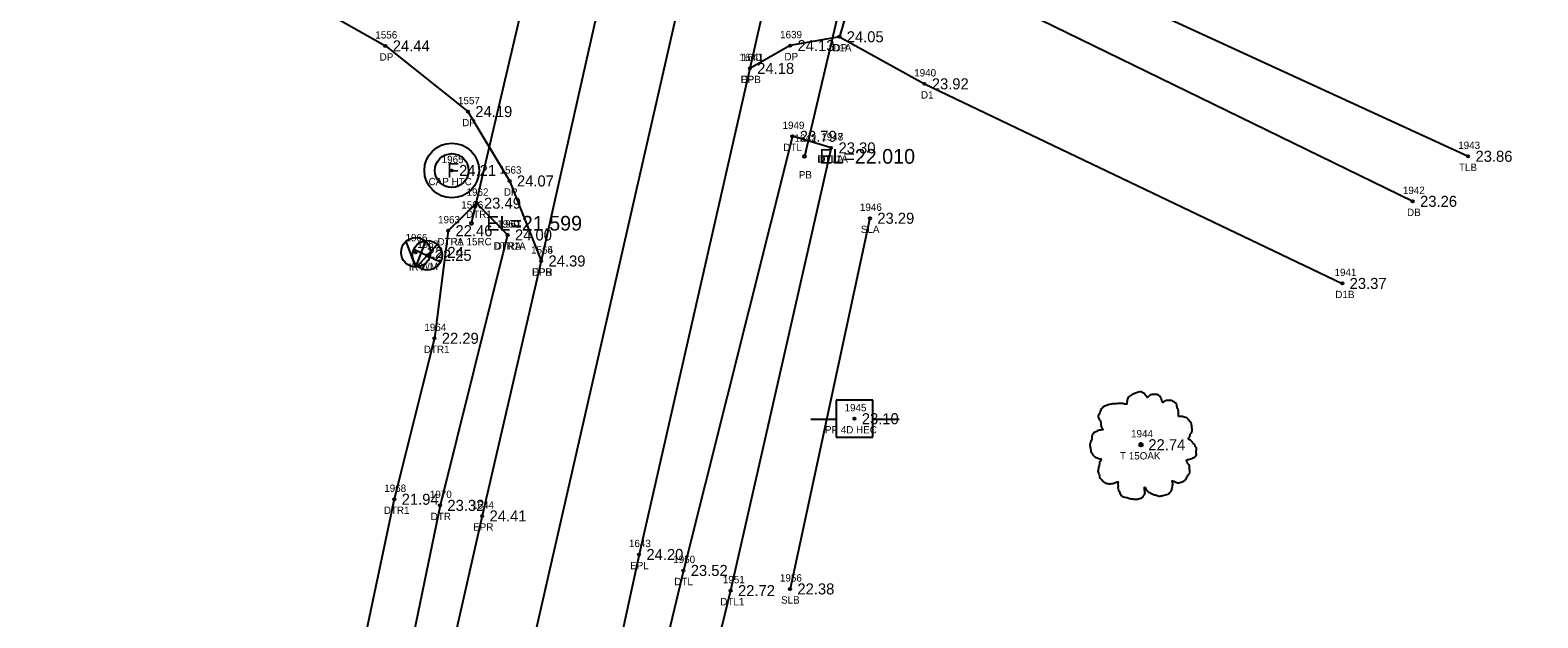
# Model space of a CAD drawing. Extents: x 2654414 to 2656963, y 761776 to 764965.
# Drawn here: x 2655478.7 to 2655683.5, y 762508.6 to 762588.5 of the extents above; entities that cross this region are included whole.
import ezdxf

# ---------------------------------------------------------------- set-up
doc = ezdxf.new("R2010")
doc.units = 0
for name, color, linetype in [('Default', 7, 'Continuous'), ('RD_EX_BldgApp', 7, 'Continuous'), ('RD_EX_BldgApp_txCode', 7, 'Continuous'), ('RD_EX_DR_Pipe', 7, 'Continuous'), ('RD_EX_DR_Pipe_txCode', 7, 'Continuous'), ('RD_EX_Driveway', 7, 'Continuous'), ('RD_EX_Driveway_txCode', 7, 'Continuous'), ('RD_EX_H2O', 7, 'Continuous'), ('RD_EX_H2O_txCode', 7, 'Continuous'), ('RD_EX_Misc_txCode', 7, 'Continuous'), ('RD_EX_Road', 7, 'Continuous'), ('RD_EX_Road_txCode', 7, 'Continuous'), ('RD_EX_TX_BldgApp_ELEV', 7, 'Continuous'), ('RD_EX_TX_Driveway_ELEV', 7, 'Continuous'), ('RD_EX_TX_H2O_ELEV', 7, 'Continuous'), ('RD_EX_TX_Misc_ELEV', 7, 'Continuous'), ('RD_EX_TX_Road_ELEV', 7, 'Continuous'), ('RD_EX_TX_UT_ELEV', 7, 'Continuous'), ('RD_EX_TX_VEG_ELEV', 7, 'Continuous'), ('RD_EX_UT', 7, 'Continuous'), ('RD_EX_UT_txCode', 7, 'Continuous'), ('RD_EX_VEG', 7, 'Continuous'), ('RD_EX_VEG_txCode', 7, 'Continuous'), ('RD_HC_Cl', 7, 'Continuous'), ('RD_HC_Survey_ELEV', 7, 'Continuous'), ('RD_SMD_Locator', 7, 'Continuous'), ('RD_TX_Pipe_ElevEX', 7, 'Continuous')]:
    doc.layers.add(name, color=color, linetype=linetype)

msp = doc.modelspace()

# ---------------------------------------------------------------- linework, layer by layer
at = {"layer": 'Default'}
msp.add_line((2656050.51, 764712.37), (2655383.26, 761787.51), dxfattribs=at)
at = {"layer": 'RD_EX_BldgApp'}
for q in [(2655529.77, 762559.8), (2655532.4, 762559.76)]:
    msp.add_line((2655531.08, 762556.31), q, dxfattribs=at)
for centre, radius in [((2655535.96, 762569.44), 3.72), ((2655535.96, 762569.44), 2.29), ((2655531.08, 762558.31), 2), ((2655531.08, 762558.31), 0.15)]:
    msp.add_circle(centre, radius, dxfattribs=at)
at = {"layer": 'RD_EX_DR_Pipe'}
for p, q in [((2655591.31, 762603.09), (2655583.89, 762571.36)), ((2655538.65, 762562.27), (2655546.14, 762594.32))]:
    msp.add_line(p, q, dxfattribs=at)
at = {"layer": 'RD_EX_Driveway'}
for points in [[(2655502.28, 762719.95), (2655507.82, 762714.48), (2655500.58, 762684.69), (2655497.67, 762681.01), (2655495.37, 762681.19), (2655493.84, 762671.94), (2655495.71, 762671.31), (2655495.21, 762667.77), (2655491.25, 762663.24), (2655487.93, 762656.49), (2655481.1, 762632.76), (2655485.71, 762616.62), (2655484.3, 762604.91), (2655505.68, 762598.43), (2655526.95, 762586.38), (2655538.16, 762577.45), (2655543.82, 762568.02), (2655548.11, 762557.14)], [(2655582.64, 762610.54), (2655588.38, 762602.83), (2655592.52, 762601.16), (2655588.62, 762587.62), (2655581.94, 762586.42), (2655576.46, 762583.32)], [(2655592.52, 762601.16), (2655603.35, 762596.15), (2655666.52, 762565.25)], [(2655588.62, 762587.62), (2655600.18, 762581.22), (2655656.95, 762554.09)]]:
    msp.add_lwpolyline(points, dxfattribs=at)
at = {"layer": 'RD_EX_H2O'}
for points in [[(2655587.51, 762572.52), (2655582.24, 762574.09), (2655567.43, 762515.07), (2655544.33, 762418.51), (2655543.66, 762411.55), (2655546.37, 762409.75), (2655549.01, 762410.21)], [(2655587.51, 762572.52), (2655573.85, 762512.33), (2655549.01, 762410.21)], [(2655543.55, 762560.68), (2655539.34, 762565), (2655535.47, 762561.26), (2655533.61, 762546.63), (2655528.16, 762524.75), (2655507.6, 762427.4), (2655486.29, 762350.37), (2655477.51, 762339.55)], [(2655543.55, 762560.68), (2655534.37, 762523.92), (2655514.09, 762425.76), (2655491.38, 762331.28), (2655488.62, 762321.94), (2655478.48, 762315.45), (2655472.03, 762316.1)]]:
    msp.add_lwpolyline(points, dxfattribs=at)
at = {"layer": 'RD_EX_Road'}
for points in [[(2655700.99, 763232.28), (2655693.55, 763198.57), (2655671.65, 763102.04), (2655649.04, 763001.06), (2655627.27, 762906.23), (2655605, 762809.37), (2655598.99, 762783.09), (2655583.65, 762714.14), (2655561.97, 762618.32), (2655556.36, 762593.84), (2655548.11, 762557.14), (2655540.1, 762522.48), (2655518.03, 762425.04), (2655496.48, 762329.56), (2655475.55, 762236.62), (2655473.2, 762226.14), (2655466.57, 762197.5), (2655460.06, 762168.16), (2655454.26, 762143.78), (2655432.5, 762049.88), (2655410.7, 761955.51), (2655388.17, 761858.43), (2655373.5, 761793.95)], [(2655670.04, 762995.18), (2655648.57, 762900.67), (2655631.27, 762824.03), (2655626.67, 762802.87), (2655621.78, 762781.91), (2655611.71, 762738.43), (2655604.93, 762708.62), (2655582.64, 762610.54), (2655576.46, 762583.32), (2655561.41, 762517.24), (2655539.15, 762414.81), (2655531.98, 762386.15), (2655517.98, 762324.29), (2655508.17, 762280.15), (2655501.46, 762251.6), (2655496.92, 762232.09), (2655477.2, 762144.97), (2655472.14, 762122.52), (2655453.74, 762045.1), (2655431.79, 761949.92), (2655409.76, 761853.25), (2655401.25, 761816.42), (2655394.61, 761787.37)]]:
    msp.add_lwpolyline(points, dxfattribs=at)
at = {"layer": 'RD_EX_UT'}
for p, q in [((2655531.29, 762556.45), (2655533.95, 762559.35)), ((2655530.81, 762558.75), (2655534.44, 762557.03)), ((2655593.17, 762538.21), (2655588.17, 762538.21)), ((2655588.17, 762538.21), (2655588.17, 762533.21)), ((2655593.17, 762533.21), (2655593.17, 762538.21)), ((2655584.73, 762535.64), (2655588.2, 762535.64)), ((2655593.09, 762535.64), (2655596.73, 762535.64)), ((2655588.17, 762533.21), (2655593.17, 762533.21))]:
    msp.add_line(p, q, dxfattribs=at)
msp.add_circle((2655532.64, 762557.91), 2, dxfattribs=at)
at = {"layer": 'RD_EX_VEG'}
msp.add_line((2655592.78, 762562.95), (2655581.92, 762512.56), dxfattribs=at)
msp.add_lwpolyline([(2655649.21, 762686), (2655618.63, 762596.91), (2655674.05, 762571.37)], dxfattribs=at)
for centre, radius in [((2655629.6, 762532.16), 0.25), ((2655629.59, 762532.15), 0.0001)]:
    msp.add_circle(centre, radius, dxfattribs=at)
for points in [[(2655629.73, 762539.33), (2655629.43, 762539.36), (2655629.11, 762539.26), (2655628.86, 762539.16), (2655628.63, 762539.08), (2655628.41, 762538.98), (2655628.11, 762538.81), (2655627.88, 762538.61), (2655627.76, 762538.36), (2655627.71, 762538.13), (2655627.66, 762537.86), (2655627.66, 762537.68), (2655627.53, 762537.66), (2655627.38, 762537.68), (2655627.13, 762537.76), (2655626.88, 762537.76), (2655626.63, 762537.76), (2655626.28, 762537.73), (2655625.93, 762537.73), (2655625.66, 762537.68), (2655625.33, 762537.63), (2655624.96, 762537.51), (2655624.61, 762537.38), (2655624.31, 762537.13), (2655624.06, 762536.66), (2655623.93, 762536.31), (2655623.78, 762536.06), (2655623.93, 762535.61), (2655624.11, 762535.26), (2655624.13, 762535.06), (2655624.21, 762534.63), (2655624.31, 762534.41), (2655624.43, 762534.21), (2655624.36, 762534.18), (2655623.98, 762534.13), (2655623.68, 762534.03), (2655623.26, 762533.81), (2655623.03, 762533.58), (2655622.93, 762533.26), (2655622.91, 762532.91), (2655622.81, 762532.71), (2655622.73, 762532.44), (2655622.71, 762532.36), (2655622.66, 762532.04), (2655622.76, 762531.59), (2655622.78, 762531.24), (2655622.91, 762531.01), (2655623.06, 762530.84), (2655623.23, 762530.59), (2655623.63, 762530.36), (2655623.96, 762530.26), (2655624.16, 762530.24), (2655623.98, 762529.74), (2655623.93, 762529.39), (2655623.81, 762528.99), (2655623.81, 762528.91), (2655623.76, 762528.44), (2655623.91, 762528.11), (2655623.98, 762527.74), (2655624.16, 762527.51), (2655624.43, 762527.21), (2655624.76, 762526.99), (2655625.26, 762526.86), (2655625.66, 762526.89), (2655626.23, 762527.06), (2655626.48, 762527.14), (2655626.46, 762526.96), (2655626.48, 762526.59), (2655626.48, 762526.16), (2655626.63, 762525.84), (2655626.73, 762525.56), (2655626.88, 762525.31), (2655627.21, 762525.09), (2655627.61, 762525.01), (2655628.03, 762524.86), (2655628.48, 762524.79), (2655628.98, 762524.76), (2655629.58, 762524.91), (2655629.86, 762525.04), (2655629.96, 762525.21), (2655630.16, 762525.59), (2655630.11, 762525.81), (2655630.13, 762526.41), (2655630.23, 762526.24), (2655630.41, 762525.89), (2655630.91, 762525.59), (2655631.31, 762525.41), (2655631.78, 762525.26), (2655632.08, 762525.19), (2655632.55, 762525.26), (2655632.93, 762525.34), (2655633.3, 762525.46), (2655633.6, 762525.74), (2655633.78, 762526.01), (2655633.83, 762526.29), (2655633.9, 762526.66), (2655633.95, 762526.84)], [(2655633.95, 762526.84), (2655633.88, 762527.01), (2655633.83, 762527.26), (2655633.9, 762527.24), (2655634.08, 762527.19), (2655634.35, 762527.06), (2655634.58, 762526.99), (2655634.9, 762527.01), (2655635.18, 762527.11), (2655635.63, 762527.39), (2655635.9, 762527.86), (2655636.18, 762528.26), (2655636.25, 762528.59), (2655636.2, 762528.81), (2655636.18, 762529.31), (2655635.98, 762529.56), (2655635.93, 762529.69), (2655635.83, 762530.09), (2655635.9, 762530.14), (2655636.18, 762530.19), (2655636.55, 762530.31), (2655636.83, 762530.44), (2655637.05, 762530.61), (2655637.13, 762530.84), (2655637.1, 762531.24), (2655637.15, 762531.64), (2655637.08, 762531.79), (2655636.98, 762531.94), (2655636.9, 762532.14), (2655636.75, 762532.29), (2655636.65, 762532.44), (2655636.55, 762532.54), (2655636.43, 762532.69), (2655636.25, 762532.81), (2655636.1, 762532.86), (2655636.05, 762533.01), (2655636.2, 762533.21), (2655636.25, 762533.31), (2655636.28, 762533.53), (2655636.5, 762533.88), (2655636.55, 762534.28), (2655636.5, 762534.71), (2655636.45, 762534.98), (2655636.3, 762535.26), (2655636.1, 762535.51), (2655635.98, 762535.68), (2655635.8, 762535.81), (2655635.48, 762535.93), (2655635.23, 762535.98), (2655634.88, 762535.98), (2655634.68, 762536.03), (2655634.7, 762536.08), (2655634.7, 762536.23), (2655634.7, 762536.51), (2655634.63, 762536.96), (2655634.48, 762537.46), (2655634.48, 762537.48), (2655634.38, 762537.73), (2655634.15, 762537.93), (2655633.98, 762538.03), (2655633.78, 762538.16), (2655633.53, 762538.18), (2655633.23, 762538.18), (2655632.95, 762538.13), (2655632.75, 762538.03), (2655632.58, 762537.91), (2655632.5, 762538.06), (2655632.4, 762538.36), (2655632.35, 762538.51), (2655632.21, 762538.68), (2655631.98, 762538.88), (2655631.53, 762539.01), (2655630.91, 762538.93), (2655630.61, 762538.73), (2655630.46, 762538.56), (2655630.41, 762538.68), (2655630.21, 762538.88), (2655630.11, 762539.06), (2655629.93, 762539.18), (2655629.78, 762539.28), (2655629.68, 762539.33)]]:
    msp.add_spline(points, degree=3, dxfattribs=at)
at = {"layer": 'RD_HC_Cl'}
msp.add_line((2656050.51, 764712.37), (2655383.26, 761787.51), dxfattribs=at)
at = {"layer": 'RD_SMD_Locator'}
for centre, radius in [((2655588.62, 762587.62), 0.15), ((2655588.62, 762587.62), 0.15), ((2655526.95, 762586.38), 0.15), ((2655581.94, 762586.42), 0.15), ((2655576.46, 762583.32), 0.15), ((2655576.46, 762583.32), 0.15), ((2655600.18, 762581.22), 0.15), ((2655538.16, 762577.45), 0.15), ((2655582.24, 762574.09), 0.15), ((2655583.89, 762571.36), 0.2), ((2655587.51, 762572.52), 0.15), ((2655587.51, 762572.52), 0.15), ((2655674.05, 762571.37), 0.15), ((2655535.96, 762569.44), 0.15), ((2655543.82, 762568.02), 0.15), ((2655539.34, 762565), 0.15), ((2655666.52, 762565.25), 0.15), ((2655592.78, 762562.95), 0.15), ((2655535.47, 762561.26), 0.15), ((2655538.65, 762562.27), 0.2), ((2655543.55, 762560.68), 0.15), ((2655543.55, 762560.68), 0.15), ((2655532.64, 762557.91), 0.15), ((2655548.11, 762557.14), 0.15), ((2655548.11, 762557.14), 0.15), ((2655656.95, 762554.09), 0.15), ((2655533.61, 762546.63), 0.15), ((2655590.67, 762535.7), 0.15), ((2655629.6, 762532.16), 0.15), ((2655528.16, 762524.75), 0.15), ((2655534.37, 762523.92), 0.15), ((2655540.1, 762522.48), 0.15), ((2655561.41, 762517.24), 0.15), ((2655567.43, 762515.07), 0.15), ((2655573.85, 762512.33), 0.15), ((2655581.92, 762512.56), 0.15)]:
    msp.add_circle(centre, radius, dxfattribs=at)

# ---------------------------------------------------------------- texts
at = {"layer": 'RD_EX_BldgApp'}
msp.add_text('F', height=2, dxfattribs=at).set_placement((2655535.32, 762568.46))
at = {"layer": 'RD_EX_BldgApp_txCode'}
for s, p in [('1965', (2655534.59, 762570.44)), ('CAP HTC', (2655532.81, 762567.44))]:
    msp.add_text(s, height=1, dxfattribs=at).set_placement(p)
at = {"layer": 'RD_EX_DR_Pipe_txCode'}
for s, p in [('1642', (2655582.52, 762573.36)), ('PB', (2655583.11, 762568.36)), ('1566', (2655537.26, 762564.27)), ('PA 15RC', (2655535.81, 762559.27))]:
    msp.add_text(s, height=1, dxfattribs=at).set_placement(p)
at = {"layer": 'RD_EX_Driveway_txCode'}
for s, p in [('1556', (2655525.58, 762587.38)), ('1639', (2655580.57, 762587.42)), ('D1A', (2655587.66, 762585.62)), ('DP', (2655587.84, 762585.62)), ('DP', (2655526.17, 762584.38)), ('1640', (2655575.05, 762584.32)), ('DP', (2655581.16, 762584.42)), ('DPB', (2655575.2, 762581.32)), ('1940', (2655598.79, 762582.22)), ('1557', (2655536.81, 762578.45)), ('D1', (2655599.71, 762579.22)), ('DP', (2655537.38, 762575.45)), ('1563', (2655542.45, 762569.02)), ('1942', (2655665.18, 762566.25)), ('DP', (2655543.04, 762566.02)), ('DB', (2655665.75, 762563.25)), ('1564', (2655546.74, 762558.14)), ('DPB', (2655546.86, 762555.14)), ('1941', (2655655.89, 762555.09)), ('D1B', (2655656, 762552.09))]:
    msp.add_text(s, height=1, dxfattribs=at).set_placement(p)
at = {"layer": 'RD_EX_H2O_txCode'}
for s, p in [('1949', (2655580.9, 762575.09)), ('1947', (2655586.17, 762573.52)), ('1948', (2655586.17, 762573.52)), ('DTL', (2655581, 762572.09)), ('DTL1A', (2655585.62, 762570.52)), ('DTLA', (2655585.78, 762570.52)), ('1962', (2655537.97, 762566)), ('1963', (2655534.1, 762562.26)), ('DTR1', (2655537.91, 762563)), ('1960', (2655542.14, 762561.68)), ('1961', (2655542.47, 762561.68)), ('DTR1', (2655534.03, 762559.26)), ('DTR1A', (2655541.63, 762558.68)), ('DTRA', (2655541.8, 762558.68)), ('1964', (2655532.24, 762547.63)), ('DTR1', (2655532.17, 762544.63)), ('1968', (2655526.79, 762525.75)), ('1970', (2655532.99, 762524.92)), ('DTR1', (2655526.73, 762522.75)), ('DTR', (2655533.1, 762521.92)), ('1950', (2655566.05, 762516.07)), ('DTL', (2655566.19, 762513.07)), ('1951', (2655572.79, 762513.33)), ('DTL1', (2655572.44, 762510.33))]:
    msp.add_text(s, height=1, dxfattribs=at).set_placement(p)
at = {"layer": 'RD_EX_Misc_txCode'}
for s, p in [('1966', (2655529.68, 762559.81)), ('IRV', (2655530.12, 762555.81))]:
    msp.add_text(s, height=1, dxfattribs=at).set_placement(p)
at = {"layer": 'RD_EX_Road_txCode'}
for s, p in [('1641', (2655575.37, 762584.32)), ('EPL', (2655575.25, 762581.32)), ('1565', (2655546.74, 762558.14)), ('EPR', (2655546.89, 762555.14)), ('1644', (2655538.73, 762523.48)), ('EPR', (2655538.87, 762520.48)), ('1643', (2655560.04, 762518.24)), ('EPL', (2655560.2, 762515.24))]:
    msp.add_text(s, height=1, dxfattribs=at).set_placement(p)
at = {"layer": 'RD_EX_TX_BldgApp_ELEV'}
msp.add_text('24.21', height=1.5, dxfattribs=at).set_placement((2655536.96, 762568.69))
at = {"layer": 'RD_EX_TX_Driveway_ELEV'}
for s, p in [('24.05', (2655589.62, 762586.87)), ('24.05', (2655589.62, 762586.87)), ('24.44', (2655527.95, 762585.63)), ('24.13', (2655582.94, 762585.67)), ('24.18', (2655577.46, 762582.57)), ('23.92', (2655601.18, 762580.47)), ('24.19', (2655539.16, 762576.7)), ('24.07', (2655544.82, 762567.27)), ('23.26', (2655667.52, 762564.5)), ('24.39', (2655549.11, 762556.39)), ('23.37', (2655657.95, 762553.34))]:
    msp.add_text(s, height=1.5, dxfattribs=at).set_placement(p)
at = {"layer": 'RD_EX_TX_H2O_ELEV'}
for s, p in [('23.79', (2655583.24, 762573.34)), ('23.30', (2655588.51, 762571.77)), ('23.30', (2655588.51, 762571.77)), ('23.49', (2655540.34, 762564.25)), ('22.46', (2655536.47, 762560.51)), ('24.00', (2655544.55, 762559.93)), ('24.00', (2655544.55, 762559.93)), ('22.29', (2655534.61, 762545.88)), ('21.94', (2655529.16, 762524)), ('23.32', (2655535.37, 762523.17)), ('23.52', (2655568.43, 762514.32)), ('22.72', (2655574.85, 762511.58))]:
    msp.add_text(s, height=1.5, dxfattribs=at).set_placement(p)
at = {"layer": 'RD_EX_TX_Misc_ELEV'}
msp.add_text('22.24', height=1.5, dxfattribs=at).set_placement((2655532.58, 762557.56))
at = {"layer": 'RD_EX_TX_Road_ELEV'}
for s, p in [('24.18', (2655577.46, 762582.57)), ('24.39', (2655549.11, 762556.39)), ('24.41', (2655541.1, 762521.73)), ('24.20', (2655562.41, 762516.49))]:
    msp.add_text(s, height=1.5, dxfattribs=at).set_placement(p)
at = {"layer": 'RD_EX_TX_UT_ELEV'}
msp.add_text('22.25', height=1.5, dxfattribs=at).set_placement((2655533.64, 762557.16))
at = {"layer": 'RD_EX_TX_VEG_ELEV'}
for s, p in [('23.86', (2655675.05, 762570.62)), ('23.29', (2655593.78, 762562.2)), ('22.74', (2655630.6, 762531.41)), ('22.38', (2655582.92, 762511.81))]:
    msp.add_text(s, height=1.5, dxfattribs=at).set_placement(p)
at = {"layer": 'RD_EX_UT_txCode'}
for s, p in [('1967', (2655531.27, 762558.91)), ('WM', (2655531.73, 762555.91)), ('1945', (2655589.33, 762536.7)), ('PP 4D HEC', (2655586.66, 762533.7))]:
    msp.add_text(s, height=1, dxfattribs=at).set_placement(p)
at = {"layer": 'RD_EX_VEG_txCode'}
for s, p in [('1943', (2655672.7, 762572.37)), ('TLB', (2655672.8, 762569.37)), ('1946', (2655591.41, 762563.95)), ('SLA', (2655591.54, 762560.95)), ('1944', (2655628.25, 762533.16)), ('T 15OAK', (2655626.75, 762530.16)), ('1956', (2655580.55, 762513.56)), ('SLB', (2655580.7, 762510.56))]:
    msp.add_text(s, height=1, dxfattribs=at).set_placement(p)
at = {"layer": 'RD_HC_Survey_ELEV'}
msp.add_text('23.10', height=1.5, dxfattribs=at).set_placement((2655591.67, 762534.95))
at = {"layer": 'RD_TX_Pipe_ElevEX'}
for s, p in [('EL=22.010', (2655585.89, 762570.36)), ('EL=21.599', (2655540.65, 762561.27))]:
    msp.add_text(s, height=2, dxfattribs=at).set_placement(p)

doc.saveas('drawing.dxf')
